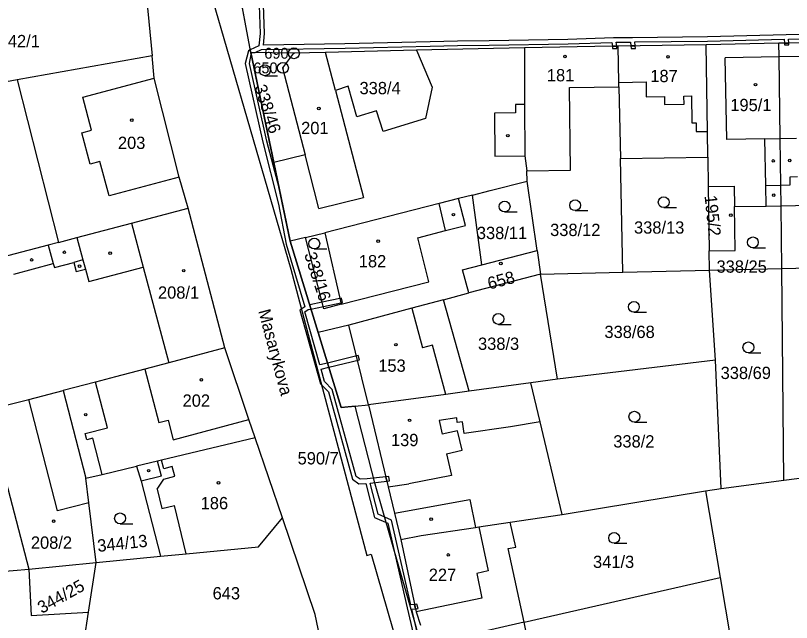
# Model space of a CAD drawing. Extents: x -758582 to -751794, y -998770 to -994350.
# Drawn here: x -755939 to -755831.8, y -995423.8 to -995339.9 of the extents above; entities that cross this region are included whole.
import ezdxf

# ---------------------------------------------------------------- set-up
doc = ezdxf.new("R2010")
doc.units = 0
for name, color, linetype in [('Hranice parcel', 7, 'Continuous'), ('Parcelní čísla', 7, 'Continuous'), ('Pop  PČ popisy', 7, 'Continuous'), ('Vnitřní kresba', 7, 'Continuous'), ('Věcná břemena k části', 7, 'Continuous'), ('Značky bodu BP', 7, 'Continuous'), ('Značky budov', 7, 'Continuous'), ('Značky kultur', 7, 'Continuous')]:
    doc.layers.add(name, color=color, linetype=linetype)

msp = doc.modelspace()

# ---------------------------------------------------------------- linework, layer by layer
at = {"layer": 'Hranice parcel'}
for p, q in [((-755883.6, -995344.69), (-755896.2, -995345)), ((-755868.69, -995344.33), (-755883.6, -995344.69)), ((-755843.58, -995343.92), (-755855.72, -995344.11)), ((-755833.54, -995343.72), (-755843.58, -995343.92)), ((-755920.16, -995345.46), (-755938.83, -995348.79)), ((-755900.63, -995345.07), (-755906.53, -995344.97)), ((-755906.53, -995344.97), (-755903.35, -995360.2)), ((-755896.2, -995345), (-755900.63, -995345.07)), ((-755938.83, -995348.79), (-755951.55, -995351.05)), ((-755938.83, -995348.79), (-755933.12, -995371.25)), ((-755855.63, -995349.73), (-755855.43, -995359.66)), ((-755855.43, -995359.66), (-755843.34, -995359.45)), ((-755855.1, -995375.38), (-755855.43, -995359.66)), ((-755843.34, -995359.45), (-755843.28, -995363.52)), ((-755903.35, -995360.2), (-755901.07, -995371.06)), ((-755868.31, -995362.8), (-755868.35, -995361.37)), ((-755866.95, -995372.36), (-755868.31, -995362.8)), ((-755843.28, -995363.52), (-755843.14, -995372.42)), ((-755874.59, -995374.33), (-755875.88, -995364.7)), ((-755833.22, -995366.18), (-755822.74, -995365.98)), ((-755910.12, -995385.83), (-755915.19, -995366.53)), ((-755833.1, -995374.88), (-755833.22, -995366.18)), ((-755898.94, -995370.56), (-755896.27, -995369.93)), ((-755898.94, -995370.56), (-755901.07, -995371.06)), ((-755901.07, -995371.06), (-755897.21, -995383.72)), ((-755874.59, -995374.33), (-755866.95, -995372.36)), ((-755866.95, -995372.36), (-755866.48, -995375.63)), ((-755843.1, -995375.11), (-755843.14, -995372.42)), ((-755833.1, -995374.88), (-755822.67, -995374.63)), ((-755866.48, -995375.63), (-755876.4, -995378.21)), ((-755866.48, -995375.63), (-755855.1, -995375.38)), ((-755864.14, -995390.18), (-755866.48, -995375.63)), ((-755855.1, -995375.38), (-755843.1, -995375.11)), ((-755843.1, -995375.11), (-755833.1, -995374.88)), ((-755842.3, -995387.53), (-755843.1, -995375.11)), ((-755832.84, -995404.14), (-755833.1, -995374.88)), ((-755879.88, -995379.18), (-755876.4, -995378.21)), ((-755876.34, -995391.84), (-755879.88, -995379.18)), ((-755842.3, -995387.53), (-755864.14, -995390.18)), ((-755841.48, -995405.26), (-755842.3, -995387.53)), ((-755867.79, -995390.68), (-755876.34, -995391.84)), ((-755864.14, -995390.18), (-755867.79, -995390.68)), ((-755932.45, -995391.73), (-755929.34, -995403.86)), ((-755890.23, -995393.72), (-755887.52, -995405.04)), ((-755942.97, -995394.4), (-755937.22, -995416.42)), ((-755902.16, -995409.32), (-755905.91, -995398.25)), ((-755832.84, -995404.14), (-755822.55, -995402.8)), ((-755841.48, -995405.26), (-755832.84, -995404.14)), ((-755887.52, -995405.04), (-755886.65, -995408.68)), ((-755863.49, -995408.86), (-755843.65, -995405.61)), ((-755843.65, -995405.61), (-755841.48, -995405.26)), ((-755843.65, -995405.61), (-755841.64, -995417.57)), ((-755886.65, -995408.68), (-755885.78, -995412.31)), ((-755870.66, -995409.94), (-755863.49, -995408.86)), ((-755927.9, -995415.52), (-755919.01, -995414.65)), ((-755958.43, -995418.29), (-755937.22, -995416.42)), ((-755937.22, -995416.42), (-755927.9, -995415.52)), ((-755928.94, -995422.38), (-755927.9, -995415.52)), ((-755868.75, -995423.76), (-755841.64, -995417.57)), ((-755841.64, -995417.57), (-755838.55, -995435.99)), ((-755929.72, -995427.54), (-755928.94, -995422.38)), ((-755867.75, -995428.48), (-755868.75, -995423.76))]:
    msp.add_line(p, q, dxfattribs=at)
for points in [[(-755924.19, -995302.25), (-755922.52, -995321.21), (-755920.16, -995345.46)], [(-755906.53, -995344.97), (-755908.71, -995333.1), (-755905.54, -995333)], [(-755822.92, -995343.49), (-755832.14, -995343.69), (-755832.74, -995343.7), (-755833.54, -995343.72)], [(-755883.6, -995344.69), (-755881.43, -995349.78), (-755882.37, -995354.11), (-755888.22, -995355.9), (-755889.13, -995353.04), (-755891.86, -995353.89), (-755893.06, -995349.65), (-755894.82, -995350.26), (-755896.2, -995345)], [(-755855.72, -995344.11), (-755855.91, -995344.11), (-755856.51, -995344.12), (-755868.69, -995344.33)], [(-755868.69, -995344.33), (-755868.67, -995352.2), (-755868.65, -995359.3), (-755868.35, -995361.37)], [(-755855.63, -995349.73), (-755855.64, -995349.13), (-755855.72, -995344.11)], [(-755843.34, -995359.45), (-755843.4, -995355.9), (-755843.58, -995343.92)], [(-755833.22, -995366.18), (-755833.26, -995363.34), (-755833.35, -995356.89), (-755833.49, -995345.61), (-755833.54, -995343.72)], [(-755915.19, -995366.53), (-755916.4, -995362.23), (-755919.86, -995348.56), (-755920.16, -995345.46)], [(-755900.63, -995345.07), (-755902.13, -995347.09), (-755899.01, -995359.16), (-755903.35, -995360.2)], [(-755868.35, -995361.37), (-755862.31, -995361.28), (-755862.48, -995349.83), (-755855.63, -995349.73)], [(-755875.88, -995364.7), (-755873.41, -995364.06), (-755868.31, -995362.8)], [(-755843.28, -995363.52), (-755839.68, -995363.47), (-755839.64, -995366.3)], [(-755875.88, -995364.7), (-755877.8, -995365.19), (-755880.49, -995365.88), (-755896.27, -995369.93)], [(-755933.12, -995371.25), (-755930.55, -995370.57), (-755923.02, -995368.57), (-755915.19, -995366.53)], [(-755843.14, -995372.42), (-755839.55, -995372.37), (-755839.64, -995366.3)], [(-755839.64, -995366.3), (-755835.27, -995366.22), (-755833.22, -995366.18)], [(-755896.27, -995369.93), (-755894.03, -995379.8), (-755896.41, -995380.42), (-755898.94, -995370.56)], [(-755933.12, -995371.25), (-755934.52, -995371.62), (-755939.98, -995373.07), (-755945.73, -995374.6)], [(-755876.4, -995378.21), (-755877.27, -995375.02), (-755874.59, -995374.33)], [(-755879.88, -995379.18), (-755884.25, -995380.36), (-755892.99, -995382.7), (-755897.21, -995383.72)], [(-755897.21, -995383.72), (-755894.05, -995394.1), (-755890.23, -995393.72)], [(-755910.12, -995385.83), (-755917.85, -995387.89), (-755921.18, -995388.78), (-755925.21, -995389.86), (-755928, -995390.58), (-755932.45, -995391.73)], [(-755905.91, -995398.25), (-755906.77, -995395.72), (-755910.12, -995385.83)], [(-755863.49, -995408.86), (-755866.52, -995396.05), (-755867.79, -995390.68)], [(-755942.97, -995394.4), (-755937.2, -995392.95), (-755932.45, -995391.73)], [(-755876.34, -995391.84), (-755879.58, -995392.28), (-755890.23, -995393.72)], [(-755905.91, -995398.25), (-755918.86, -995401.36), (-755919.43, -995401.5), (-755922.3, -995402.18)], [(-755929.34, -995403.86), (-755927.08, -995403.32), (-755922.3, -995402.18)], [(-755922.3, -995402.18), (-755921.69, -995404.26), (-755919.01, -995414.65)], [(-755927.9, -995415.52), (-755928.92, -995407.24), (-755929.34, -995403.86)], [(-755919.01, -995414.65), (-755915.44, -995414.3), (-755905.44, -995413.35), (-755902.16, -995409.32)], [(-755883.45, -995499.55), (-755884.46, -995485.87), (-755897.62, -995422.7), (-755902.16, -995409.32)], [(-755885.78, -995412.31), (-755882.98, -995411.79), (-755875.44, -995410.66), (-755875, -995410.59), (-755870.66, -995409.94)], [(-755868.75, -995423.76), (-755870.92, -995413.56), (-755869.9, -995413.37), (-755870.66, -995409.94)], [(-755885.78, -995412.31), (-755883.67, -995422.35), (-755883.04, -995424.16)], [(-755937.22, -995416.42), (-755936.87, -995422.83), (-755928.94, -995422.38)]]:
    msp.add_lwpolyline(points, dxfattribs=at)
at = {"layer": 'Vnitřní kresba'}
for p, q in [((-755833.49, -995345.61), (-755840.96, -995345.75)), ((-755840.72, -995357.04), (-755840.96, -995345.75)), ((-755826.03, -995345.47), (-755833.49, -995345.61)), ((-755929.75, -995351.19), (-755919.86, -995348.56)), ((-755855.64, -995349.13), (-755851.88, -995349.07)), ((-755851.88, -995349.07), (-755851.85, -995351.1)), ((-755894.82, -995350.26), (-755890.93, -995365.03)), ((-755851.85, -995351.1), (-755849.35, -995351.06)), ((-755849.35, -995351.06), (-755849.33, -995352.16)), ((-755846.65, -995351.02), (-755845.6, -995351)), ((-755846.63, -995352.12), (-755846.65, -995351.02)), ((-755845.6, -995351), (-755845.54, -995354.73)), ((-755928.54, -995355.73), (-755929.75, -995351.19)), ((-755868.67, -995352.2), (-755869.92, -995352.2)), ((-755869.92, -995352.2), (-755869.92, -995353.35)), ((-755849.33, -995352.16), (-755846.63, -995352.12)), ((-755869.92, -995353.35), (-755872.82, -995353.36)), ((-755872.82, -995353.36), (-755872.8, -995359.31)), ((-755845.54, -995354.73), (-755844.96, -995354.72)), ((-755844.96, -995354.72), (-755844.95, -995355.92)), ((-755929.89, -995356.09), (-755928.54, -995355.73)), ((-755928.74, -995360.44), (-755929.89, -995356.09)), ((-755844.95, -995355.92), (-755843.4, -995355.9)), ((-755835.47, -995356.93), (-755840.72, -995357.04)), ((-755835.47, -995356.93), (-755833.35, -995356.89)), ((-755835.33, -995363.38), (-755835.47, -995356.93)), ((-755833.35, -995356.89), (-755831.07, -995356.84)), ((-755897.1, -995366.54), (-755899.01, -995359.16)), ((-755872.8, -995359.31), (-755868.65, -995359.3)), ((-755927.38, -995360.08), (-755928.74, -995360.44)), ((-755926.12, -995364.82), (-755927.38, -995360.08)), ((-755916.4, -995362.23), (-755926.12, -995364.82)), ((-755831.98, -995362.17), (-755830.96, -995362.15)), ((-755831.95, -995363.31), (-755831.98, -995362.17)), ((-755835.33, -995363.38), (-755833.26, -995363.34)), ((-755835.27, -995366.22), (-755835.33, -995363.38)), ((-755833.26, -995363.34), (-755831.95, -995363.31)), ((-755897.1, -995366.54), (-755890.93, -995365.03)), ((-755879.61, -995369.62), (-755880.49, -995365.88)), ((-755876.83, -995368.89), (-755877.8, -995365.19)), ((-755923.02, -995368.57), (-755921.39, -995374.66)), ((-755879.61, -995369.62), (-755876.83, -995368.89)), ((-755883.43, -995370.64), (-755879.61, -995369.62)), ((-755930.55, -995370.57), (-755929.72, -995373.68)), ((-755881.93, -995376.69), (-755883.43, -995370.64)), ((-755934.52, -995371.62), (-755933.84, -995374.16)), ((-755939.3, -995375.62), (-755933.84, -995374.16)), ((-755933.84, -995374.16), (-755933.68, -995374.74)), ((-755933.68, -995374.74), (-755930.98, -995374.01)), ((-755929.72, -995373.68), (-755930.98, -995374.01)), ((-755930.98, -995374.01), (-755930.64, -995375.27)), ((-755929.72, -995373.68), (-755929.39, -995374.93)), ((-755928.92, -995376.67), (-755921.39, -995374.66)), ((-755921.39, -995374.66), (-755917.85, -995387.89)), ((-755930.64, -995375.27), (-755929.39, -995374.93)), ((-755929.39, -995374.93), (-755928.92, -995376.67)), ((-755894.03, -995379.8), (-755881.93, -995376.69)), ((-755884.25, -995380.36), (-755882.79, -995385.83)), ((-755890.23, -995393.72), (-755892.99, -995382.7)), ((-755881.4, -995385.46), (-755882.79, -995385.83)), ((-755879.58, -995392.28), (-755881.4, -995385.46)), ((-755921.18, -995388.78), (-755919.22, -995396.16)), ((-755926.35, -995396.88), (-755928, -995390.58)), ((-755933.23, -995408.35), (-755937.2, -995392.95)), ((-755919.22, -995396.16), (-755917.96, -995395.82)), ((-755917.96, -995395.82), (-755917.23, -995398.57)), ((-755917.23, -995398.57), (-755906.77, -995395.72)), ((-755878.06, -995395.52), (-755880.49, -995395.89)), ((-755880.49, -995395.89), (-755880.07, -995397.75)), ((-755877.97, -995396.16), (-755878.06, -995395.52)), ((-755877.27, -995396.05), (-755877.97, -995396.16)), ((-755877.03, -995397.67), (-755877.27, -995396.05)), ((-755866.52, -995396.05), (-755870.63, -995396.73)), ((-755929.43, -995397.68), (-755926.35, -995396.88)), ((-755870.63, -995396.73), (-755877.03, -995397.67)), ((-755929.2, -995398.55), (-755929.43, -995397.68)), ((-755877.94, -995397.29), (-755880.07, -995397.75)), ((-755877.31, -995399.98), (-755877.94, -995397.29)), ((-755928.38, -995398.34), (-755929.2, -995398.55)), ((-755927.08, -995403.32), (-755928.38, -995398.34)), ((-755879.45, -995400.47), (-755877.31, -995399.98)), ((-755879.45, -995400.47), (-755878.78, -995403.46)), ((-755918.86, -995403.56), (-755919.43, -995401.5)), ((-755918.53, -995402.55), (-755918.86, -995401.36)), ((-755917.41, -995402.24), (-755918.53, -995402.55)), ((-755917.04, -995403.58), (-755917.41, -995402.24)), ((-755918.86, -995403.56), (-755921.69, -995404.26)), ((-755918.52, -995404), (-755917.04, -995403.58)), ((-755878.78, -995403.46), (-755884.68, -995404.63)), ((-755919.48, -995405.38), (-755918.52, -995404)), ((-755887.52, -995405.04), (-755884.68, -995404.63)), ((-755919.48, -995405.38), (-755918.83, -995408.05)), ((-755886.65, -995408.68), (-755876.26, -995406.79)), ((-755876.26, -995406.79), (-755875.44, -995410.66)), ((-755928.92, -995407.24), (-755933.23, -995408.35)), ((-755918.83, -995408.05), (-755917.08, -995407.62)), ((-755915.44, -995414.3), (-755917.08, -995407.62)), ((-755875, -995410.59), (-755873.72, -995416.68)), ((-755873.72, -995416.68), (-755875.29, -995417.01)), ((-755875.29, -995417.01), (-755874.57, -995420.44)), ((-755874.57, -995420.44), (-755883.67, -995422.35)), ((-755868.75, -995423.76), (-755875.56, -995425.32))]:
    msp.add_line(p, q, dxfattribs=at)
at = {"layer": 'Věcná břemena k části'}
for points in [[(-755881.16, -995437.25), (-755882.26, -995429.56), (-755883.75, -995424.07), (-755889.32, -995404.7), (-755892.08, -995393.9), (-755894.05, -995394.1), (-755897.21, -995383.72), (-755901.07, -995371.06), (-755906.53, -995344.97), (-755908.16, -995336.1), (-755909.01, -995335.45), (-755912.24, -995336.2), (-755901, -995374.96), (-755890.47, -995414.52), (-755889.87, -995414.36), (-755886.83, -995424.93), (-755883.66, -995436.65), (-755881.9, -995437.96)], [(-755855.91, -995344.11), (-755856.51, -995344.12), (-755856.53, -995344.44), (-755855.93, -995344.44)], [(-755853.38, -995344.07), (-755853.98, -995344.08), (-755853.95, -995344.44), (-755853.35, -995344.43)], [(-755832.14, -995343.69), (-755832.74, -995343.7), (-755832.72, -995343.95), (-755832.12, -995343.95)], [(-755898.38, -995379.9), (-755898.2, -995380.47), (-755896.49, -995380.11), (-755894.08, -995379.6), (-755893.84, -995379.55), (-755893.96, -995378.96), (-755894.21, -995379.01), (-755896.64, -995379.53)], [(-755895.93, -995387.94), (-755895.75, -995388.51), (-755891.5, -995387.48), (-755891.67, -995386.9)], [(-755887.44, -995403.63), (-755887.85, -995403.67), (-755887.71, -995404.26), (-755887.35, -995404.22)], [(-755883.89, -995421.32), (-755883.76, -995421.91), (-755883.4, -995421.86), (-755883.55, -995421.28)]]:
    msp.add_lwpolyline(points, close=True, dxfattribs=at)
for points in [[(-755905.45, -995335.88), (-755905.21, -995342.35), (-755905.39, -995344.09), (-755906.59, -995344.63), (-755906.53, -995344.97), (-755905.9, -995344.98), (-755905.02, -995344.58), (-755893.49, -995344.38), (-755881.73, -995344.13), (-755877.94, -995344.04), (-755873.56, -995343.98), (-755862.67, -995343.81), (-755856.61, -995343.59), (-755856.51, -995344.12), (-755855.91, -995344.11), (-755856, -995343.57), (-755854.02, -995343.54), (-755853.98, -995344.08), (-755853.38, -995344.07), (-755853.42, -995343.53), (-755843.39, -995343.42), (-755832.79, -995343.17), (-755832.74, -995343.7), (-755832.14, -995343.69), (-755832.19, -995343.16), (-755821, -995342.92)], [(-755820.95, -995342.32), (-755832.52, -995342.56), (-755843.4, -995342.82), (-755853.75, -995342.94), (-755856.37, -995342.98), (-755862.68, -995343.21), (-755873.57, -995343.38), (-755877.95, -995343.44), (-755881.74, -995343.53), (-755893.5, -995343.78), (-755904.77, -995343.98), (-755904.61, -995342.37), (-755904.86, -995335.72)], [(-755882.87, -995427.93), (-755884.24, -995421.96), (-755883.76, -995421.91), (-755883.89, -995421.32), (-755884.38, -995421.37), (-755887.06, -995409.66), (-755888.91, -995408.85), (-755890.03, -995404.52), (-755887.71, -995404.26), (-755887.85, -995403.67), (-755890.43, -995403.96), (-755891.42, -995404.01), (-755891.96, -995403.61), (-755895.27, -995391.6), (-755896.33, -995390.5), (-755896.81, -995388.77), (-755895.75, -995388.51), (-755895.93, -995387.94), (-755896.97, -995388.19), (-755899.04, -995380.87), (-755898.57, -995380.55), (-755898.2, -995380.47), (-755898.38, -995379.9), (-755901.07, -995371.06), (-755902.11, -995366.12), (-755902.23, -995365.54), (-755902.57, -995363.9), (-755904.29, -995357.26), (-755906.68, -995346.5), (-755906.46, -995345.29), (-755906.59, -995344.63), (-755906.84, -995344.75), (-755907.29, -995346.51), (-755904.87, -995357.4), (-755902.67, -995365.94), (-755901.64, -995371.51), (-755899.04, -995380.14), (-755899.73, -995380.62), (-755896.87, -995390.81), (-755895.8, -995391.9), (-755892.48, -995403.97), (-755891.6, -995404.62), (-755890.63, -995404.57), (-755889.42, -995409.29), (-755887.58, -995410.09), (-755884.9, -995421.77), (-755883.45, -995428.1)]]:
    msp.add_lwpolyline(points, dxfattribs=at)
at = {"layer": 'Značky bodu BP'}
for centre, radius in [((-755900.55, -995345.1), 0.75), ((-755900.55, -995345.1), 0.03), ((-755902.07, -995347.12), 0.75), ((-755902.07, -995347.12), 0.03)]:
    msp.add_circle(centre, radius, dxfattribs=at)
at = {"layer": 'Značky budov'}
for centre in [(-755863.09, -995345.54), (-755848.84, -995345.59), (-755836.75, -995349.44), (-755897.12, -995352.73), (-755922.98, -995354.34), (-755870.98, -995356.5), (-755834.29, -995359.98), (-755832.02, -995359.92), (-755834.23, -995364.71), (-755878.51, -995367.42), (-755840.16, -995367.49), (-755888.91, -995371.08), (-755932.29, -995372.61), (-755925.97, -995372.74), (-755936.82, -995373.67), (-755930.19, -995374.54), (-755871.96, -995374.16), (-755915.8, -995375.15), (-755886.46, -995385.39), (-755913.35, -995390.26), (-755929.34, -995395.07), (-755884.57, -995395.86), (-755920.64, -995402.81), (-755910.99, -995404.5), (-755933.78, -995409.79), (-755881.59, -995409.52), (-755879.22, -995414.46)]:
    msp.add_circle(centre, 0.175, dxfattribs=at)
at = {"layer": 'Značky kultur'}
for p, q in [((-755904.58, -995348.2), (-755902.83, -995348.2)), ((-755871.43, -995367.04), (-755869.68, -995367.04)), ((-755861.68, -995366.86), (-755859.93, -995366.86)), ((-755849.44, -995366.44), (-755847.69, -995366.44)), ((-755897.75, -995372.16), (-755896, -995372.16)), ((-755837.11, -995372), (-755835.36, -995372)), ((-755853.56, -995380.91), (-755851.81, -995380.91)), ((-755872.29, -995382.59), (-755870.54, -995382.59)), ((-755837.74, -995386.52), (-755835.99, -995386.52)), ((-755853.5, -995396.1), (-755851.75, -995396.1)), ((-755924.59, -995410.16), (-755922.84, -995410.16)), ((-755856.29, -995412.86), (-755854.54, -995412.86))]:
    msp.add_line(p, q, dxfattribs=at)
for centre in [(-755904.58, -995347.45), (-755849.44, -995365.69), (-755871.43, -995366.29), (-755861.68, -995366.11), (-755897.75, -995371.41), (-755837.11, -995371.25), (-755853.56, -995380.16), (-755872.29, -995381.84), (-755837.74, -995385.77), (-755853.5, -995395.35), (-755924.59, -995409.41), (-755856.29, -995412.11)]:
    msp.add_circle(centre, 0.75, dxfattribs=at)

# ---------------------------------------------------------------- texts
at = {"layer": 'Parcelní čísla'}
for s, p in [('642/1', (-755941.37, -995344.26)), ('181', (-755865.59, -995348.98)), ('187', (-755851.29, -995349.09)), ('338/4', (-755891.49, -995350.76)), ('195/1', (-755840.23, -995353.1)), ('201', (-755899.56, -995356.28)), ('203', (-755924.89, -995358.33)), ('338/13', (-755853.54, -995370.04)), ('338/11', (-755875.27, -995370.79)), ('338/12', (-755865.14, -995370.37)), ('182', (-755891.59, -995374.7)), ('338/25', (-755842.14, -995375.44)), ('208/1', (-755919.35, -995379.03)), ('338/68', (-755857.63, -995384.47)), ('338/3', (-755875.11, -995386.11)), ('153', (-755888.9, -995389.14)), ('338/69', (-755841.57, -995390.14)), ('202', (-755915.95, -995393.97)), ('139', (-755887.14, -995399.42)), ('338/2', (-755856.41, -995399.61)), ('590/7', (-755900.05, -995401.95)), ('186', (-755913.45, -995408.15)), ('208/2', (-755936.92, -995413.61)), ('341/3', (-755859.21, -995416.27)), ('227', (-755881.92, -995418.06)), ('643', (-755911.8, -995420.61))]:
    msp.add_text(s, height=1.7, dxfattribs=at).set_placement(p)
for s, rotation, p in [('338/46', 288, (-755906.05, -995349.74)), ('195/2', 276, (-755843.8, -995364.81)), ('338/16', 288, (-755899.16, -995372.91)), ('658', 15, (-755873.54, -995377.79)), ('344/13', 6, (-755927.65, -995414.05)), ('344/25', 29, (-755935.41, -995422.63))]:
    msp.add_text(s, height=1.7, rotation=rotation, dxfattribs=at).set_placement(p)
at = {"layer": 'Pop  PČ popisy'}
msp.add_text('Masarykova', height=1.7, rotation=285, dxfattribs=at).set_placement((-755905.51, -995380.73))
at = {"layer": 'Značky bodu BP'}
for s, p in [('690', (-755904.65, -995345.85)), ('650', (-755906.17, -995347.87))]:
    msp.add_text(s, height=1.5, dxfattribs=at).set_placement(p)

doc.saveas('drawing.dxf')
